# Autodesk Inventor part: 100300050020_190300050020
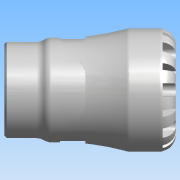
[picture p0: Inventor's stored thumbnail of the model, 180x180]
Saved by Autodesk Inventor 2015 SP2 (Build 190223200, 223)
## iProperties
Created: 2016-12
Part Number: 100300050020_190300050020
Material: PVC-Piping
Description: PLASSON FEMALE ADAPTOR 50X2" SERIES 1
Document SubType Name: Modeling
Designer: KIM
Mass: 664.223 g
Surface Area: 733.008 cm^2
Volume: 474.445 cm^3
Density: 1.4 g/cm^3
Appearance: Smooth - White
Author: KIM
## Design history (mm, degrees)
derived "1003.ipt"
feature "Solid1::1003.ipt"
tag "TaggingFeature1"
body "Solid1"
other parameters: "d0" = 118, "d1" = 32.76, "d3" = 62.5, "d4" = 85, "d6" = 78, "d8" = 72.25, "d13" = 9, "d14" = 9, "d15" = 0, "d17" = 360 deg, "d19" = 8 deg, "d20" = 1, "d21" = 1, "d22" = 8 deg, "d24" = 0, "d26" = 360 deg, "d32" = 8.5, "d33" = 8.5, "d39" = 1.69968, "d42" = 56.656, "d43" = 66.3, "d46" = 4.16667, "d47" = 29, "d48" = 53.8232, "d50" = 3.63, "d51" = 0.85, "d54" = 17.5, "d55" = 11, "d57" = 17.64, "d58" = 0, "d68" = 360 deg, "d72" = 1, "d74" = 0, "d76" = 14.875, "E_" = 85, "H_" = 118, "l_" = 78, "Rp" = 56.656, "l_2" = 29, "d9" = 11.25, "d11" = 85, "d12" = 62.5, "d49" = 11
